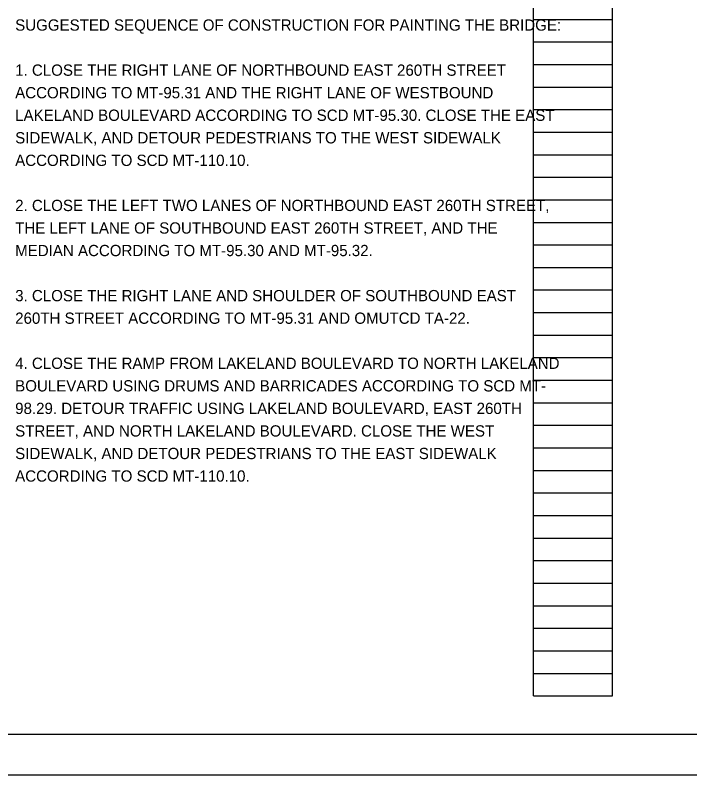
# Model space of a CAD drawing. Extents: x 0 to 34, y 0 to 22.
# Drawn here: x 17.24 to 25.62, y 0 to 9.43 of the extents above; entities that cross this region are included whole.
import ezdxf

# ---------------------------------------------------------------- set-up
doc = ezdxf.new("R2010")
doc.units = 0
for name, color, linetype in [('SH_Border', 7, 'Continuous'), ('SH_Cut_Line', 7, 'Continuous'), ('SH_Data', 7, 'Continuous'), ('SH_Text', 7, 'Continuous')]:
    doc.layers.add(name, color=color, linetype=linetype)

msp = doc.modelspace()

# ---------------------------------------------------------------- linework, layer by layer
at = {"layer": 'SH_Border'}
msp.add_lwpolyline([(1.5, 21.5), (33.5, 21.5), (33.5, 0.5), (1.5, 0.5)], close=True, dxfattribs=at)
at = {"layer": 'SH_Cut_Line'}
msp.add_lwpolyline([(0, 0), (34, 0), (34, 22), (0, 22)], close=True, dxfattribs=at)
at = {"layer": 'SH_Data'}
for p, q in [((23.68, 0.98), (23.68, 21.14)), ((24.66, 0.98), (24.66, 21.14)), ((23.68, 9.38), (24.66, 9.38)), ((23.68, 9.1), (24.66, 9.1)), ((23.68, 8.82), (24.66, 8.82)), ((23.68, 8.54), (24.66, 8.54)), ((23.68, 8.26), (24.66, 8.26)), ((23.68, 7.98), (24.66, 7.98)), ((23.68, 7.7), (24.66, 7.7)), ((23.68, 7.42), (24.66, 7.42)), ((23.68, 7.14), (24.66, 7.14)), ((23.68, 6.86), (24.66, 6.86)), ((23.68, 6.58), (24.66, 6.58)), ((23.68, 6.3), (24.66, 6.3)), ((23.68, 6.02), (24.66, 6.02)), ((23.68, 5.74), (24.66, 5.74)), ((23.68, 5.46), (24.66, 5.46)), ((23.68, 5.18), (24.66, 5.18)), ((23.68, 4.9), (24.66, 4.9)), ((23.68, 4.62), (24.66, 4.62)), ((23.68, 4.34), (24.66, 4.34)), ((23.68, 4.06), (24.66, 4.06)), ((23.68, 3.78), (24.66, 3.78)), ((23.68, 3.5), (24.66, 3.5)), ((23.68, 3.22), (24.66, 3.22)), ((23.68, 2.94), (24.66, 2.94)), ((23.68, 2.66), (24.66, 2.66)), ((23.68, 2.38), (24.66, 2.38)), ((23.68, 2.1), (24.66, 2.1)), ((23.68, 1.82), (24.66, 1.82)), ((23.68, 1.54), (24.66, 1.54)), ((23.68, 1.26), (24.66, 1.26)), ((23.68, 0.98), (24.66, 0.98))]:
    msp.add_line(p, q, dxfattribs=at)

# ---------------------------------------------------------------- texts
at = {"layer": 'SH_Text'}
for s, p in [('SUGGESTED SEQUENCE OF CONSTRUCTION FOR PAINTING THE BRIDGE:', (17.24, 9.24)), ('1. CLOSE THE RIGHT LANE OF NORTHBOUND EAST 260TH STREET ', (17.24, 8.68)), ('ACCORDING TO MT-95.31 AND THE RIGHT LANE OF WESTBOUND ', (17.24, 8.4)), ('LAKELAND BOULEVARD ACCORDING TO SCD MT-95.30. CLOSE THE EAST ', (17.24, 8.12)), ('SIDEWALK, AND DETOUR PEDESTRIANS TO THE WEST SIDEWALK ', (17.24, 7.84)), ('ACCORDING TO SCD MT-110.10.', (17.24, 7.56)), ('2. CLOSE THE LEFT TWO LANES OF NORTHBOUND EAST 260TH STREET, ', (17.24, 7)), ('THE LEFT LANE OF SOUTHBOUND EAST 260TH STREET, AND THE ', (17.24, 6.72)), ('MEDIAN ACCORDING TO MT-95.30 AND MT-95.32.', (17.24, 6.44)), ('3. CLOSE THE RIGHT LANE AND SHOULDER OF SOUTHBOUND EAST ', (17.24, 5.88)), ('260TH STREET ACCORDING TO MT-95.31 AND OMUTCD TA-22.', (17.24, 5.6)), ('4. CLOSE THE RAMP FROM LAKELAND BOULEVARD TO NORTH LAKELAND ', (17.24, 5.04)), ('BOULEVARD USING DRUMS AND BARRICADES ACCORDING TO SCD MT-', (17.24, 4.76)), ('98.29. DETOUR TRAFFIC USING LAKELAND BOULEVARD, EAST 260TH ', (17.24, 4.48)), ('STREET, AND NORTH LAKELAND BOULEVARD. CLOSE THE WEST ', (17.24, 4.2)), ('SIDEWALK, AND DETOUR PEDESTRIANS TO THE EAST SIDEWALK ', (17.24, 3.92)), ('ACCORDING TO SCD MT-110.10.', (17.24, 3.64))]:
    msp.add_text(s, height=0.14, dxfattribs=at).set_placement(p)

doc.saveas('drawing.dxf')
